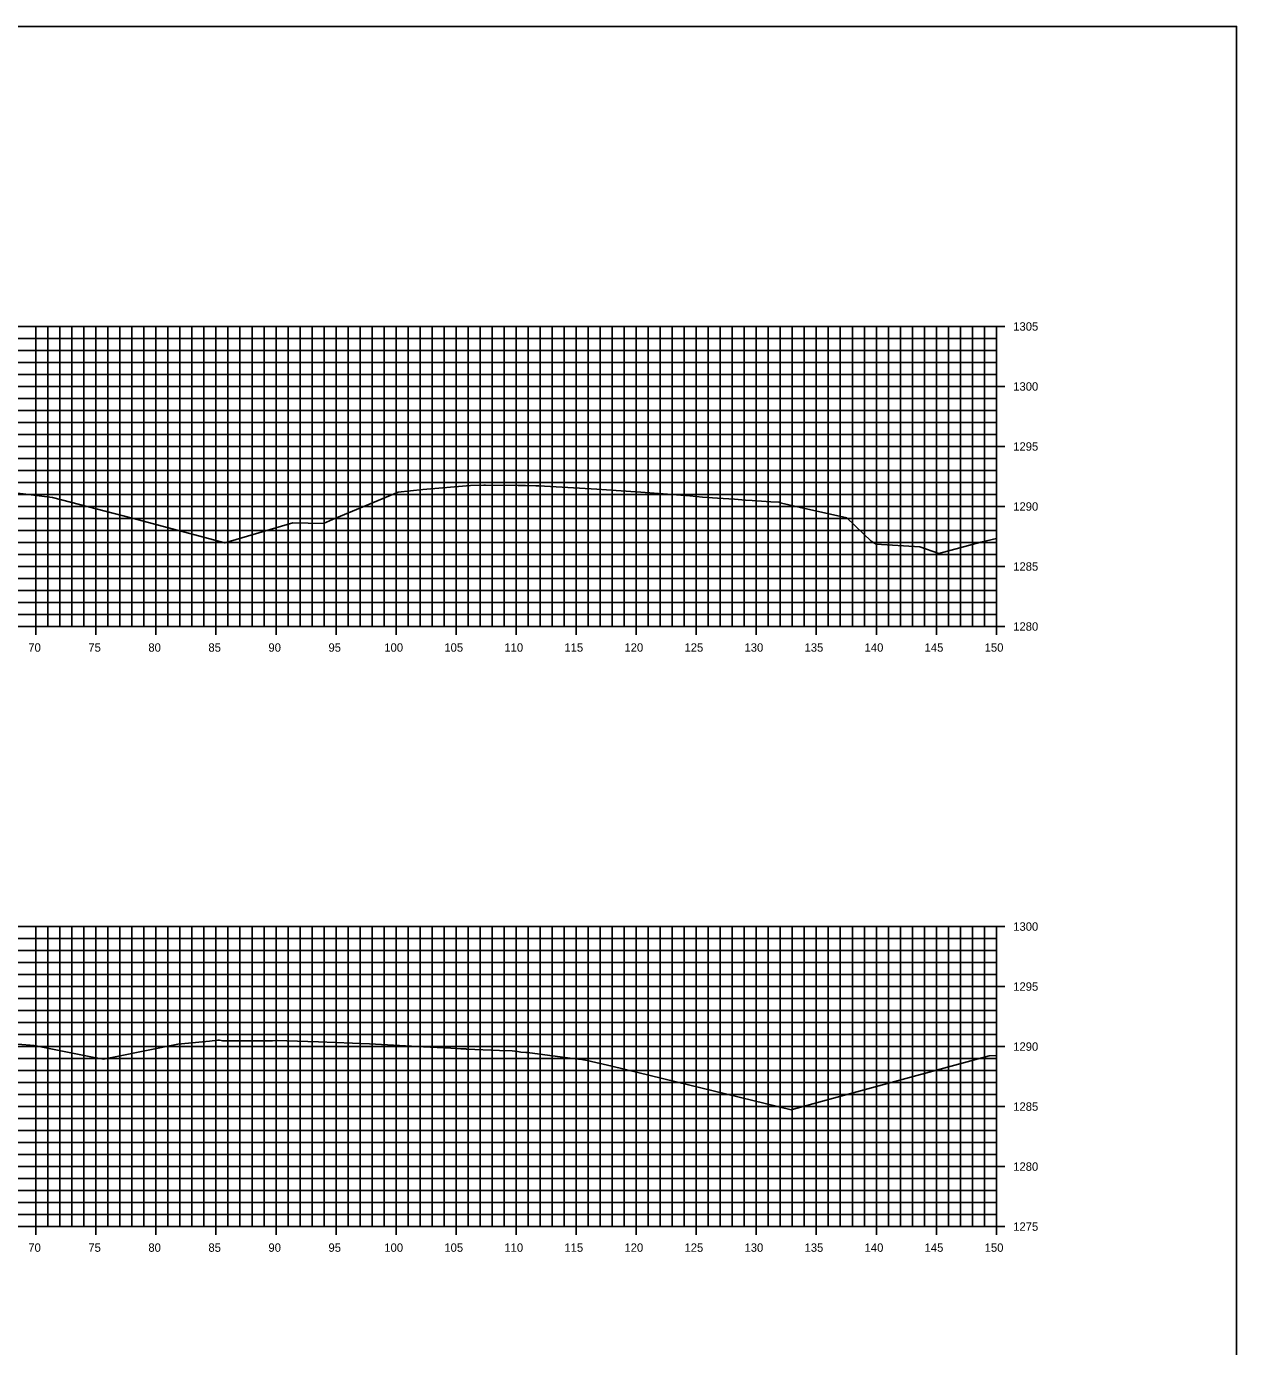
# Model space of a CAD drawing. Extents: x 674939 to 678919, y 750652 to 765176.
# Drawn here: x 678817.7 to 678918.5, y 757702.6 to 757812.6 of the extents above; entities that cross this region are included whole.
import ezdxf

# ---------------------------------------------------------------- set-up
doc = ezdxf.new("R2010")
doc.units = 0
for name, color, linetype in [('R_Axis', 7, 'Continuous'), ('R_Axis Annot', 7, 'Continuous'), ('R_Exist Surface', 7, 'Continuous'), ('R_Grid', 7, 'Continuous'), ('R_No Plot', 7, 'Continuous')]:
    doc.layers.add(name, color=color, linetype=linetype)

msp = doc.modelspace()

# ---------------------------------------------------------------- linework, layer by layer
at = {"layer": 'R_Axis'}
for p, q in [((678899.23, 757787.55), (678897.83, 757787.55)), ((678898.53, 757762.55), (678898.53, 757787.55)), ((678899.23, 757782.55), (678897.83, 757782.55)), ((678899.23, 757777.55), (678897.83, 757777.55)), ((678899.23, 757772.55), (678897.83, 757772.55)), ((678899.23, 757767.55), (678897.83, 757767.55)), ((678598.53, 757762.55), (678898.53, 757762.55)), ((678818.53, 757761.85), (678818.53, 757763.25)), ((678823.53, 757761.85), (678823.53, 757763.25)), ((678828.53, 757761.85), (678828.53, 757763.25)), ((678833.53, 757761.85), (678833.53, 757763.25)), ((678838.53, 757761.85), (678838.53, 757763.25)), ((678843.53, 757761.85), (678843.53, 757763.25)), ((678848.53, 757761.85), (678848.53, 757763.25)), ((678853.53, 757761.85), (678853.53, 757763.25)), ((678858.53, 757761.85), (678858.53, 757763.25)), ((678863.53, 757761.85), (678863.53, 757763.25)), ((678868.53, 757761.85), (678868.53, 757763.25)), ((678873.53, 757761.85), (678873.53, 757763.25)), ((678878.53, 757761.85), (678878.53, 757763.25)), ((678883.53, 757761.85), (678883.53, 757763.25)), ((678888.53, 757761.85), (678888.53, 757763.25)), ((678893.53, 757761.85), (678893.53, 757763.25)), ((678899.23, 757762.55), (678897.83, 757762.55)), ((678898.53, 757761.85), (678898.53, 757763.25)), ((678899.23, 757737.55), (678897.83, 757737.55)), ((678898.53, 757712.55), (678898.53, 757737.55)), ((678899.23, 757732.55), (678897.83, 757732.55)), ((678899.23, 757727.55), (678897.83, 757727.55)), ((678899.23, 757722.55), (678897.83, 757722.55)), ((678899.23, 757717.55), (678897.83, 757717.55)), ((678818.53, 757711.85), (678818.53, 757713.25)), ((678823.53, 757711.85), (678823.53, 757713.25)), ((678828.53, 757711.85), (678828.53, 757713.25)), ((678833.53, 757711.85), (678833.53, 757713.25)), ((678838.53, 757711.85), (678838.53, 757713.25)), ((678843.53, 757711.85), (678843.53, 757713.25)), ((678848.53, 757711.85), (678848.53, 757713.25)), ((678853.53, 757711.85), (678853.53, 757713.25)), ((678858.53, 757711.85), (678858.53, 757713.25)), ((678863.53, 757711.85), (678863.53, 757713.25)), ((678868.53, 757711.85), (678868.53, 757713.25)), ((678873.53, 757711.85), (678873.53, 757713.25)), ((678878.53, 757711.85), (678878.53, 757713.25)), ((678883.53, 757711.85), (678883.53, 757713.25)), ((678888.53, 757711.85), (678888.53, 757713.25)), ((678893.53, 757711.85), (678893.53, 757713.25)), ((678898.53, 757711.85), (678898.53, 757713.25)), ((678598.53, 757712.55), (678898.53, 757712.55)), ((678899.23, 757712.55), (678897.83, 757712.55))]:
    msp.add_line(p, q, dxfattribs=at)
at = {"layer": 'R_Exist Surface'}
for points in [[(678814.53, 757773.97), (678819.91, 757773.29), (678826.55, 757771.58), (678834.27, 757769.51), (678839.92, 757771.18), (678842.49, 757771.12), (678843.23, 757771.46), (678848.7, 757773.74), (678850.76, 757773.97), (678854.73, 757774.31), (678854.73, 757774.31), (678855.83, 757774.34), (678855.97, 757774.34), (678858.71, 757774.3), (678859.2, 757774.29), (678859.31, 757774.29), (678860.17, 757774.28), (678860.42, 757774.27), (678865.25, 757773.99), (678866.87, 757773.89), (678868.92, 757773.74), (678872.99, 757773.43), (678874.05, 757773.33), (678875.3, 757773.23), (678876.72, 757773.15), (678877.64, 757773.09), (678878.19, 757773.06), (678879.73, 757772.95), (678880.43, 757772.9), (678880.53, 757772.85), (678880.64, 757772.84), (678882.21, 757772.46), (678886.07, 757771.6), (678888.11, 757769.65), (678888.51, 757769.41), (678892.15, 757769.19), (678893.72, 757768.63), (678897.24, 757769.57), (678898.53, 757769.89)], [(678815.66, 757727.87), (678818.38, 757727.65), (678823.24, 757726.68), (678824.15, 757726.51), (678825.27, 757726.72), (678830.36, 757727.74), (678832.98, 757728), (678833.69, 757728.09), (678833.82, 757728.07), (678834.09, 757728.02), (678835.63, 757728.03), (678837.96, 757728.04), (678838.25, 757728.04), (678838.65, 757728.05), (678839.43, 757728.04), (678842.07, 757727.94), (678846.32, 757727.77), (678850.82, 757727.54), (678853.08, 757727.41), (678853.91, 757727.37), (678854.21, 757727.35), (678854.34, 757727.35), (678854.39, 757727.34), (678857.14, 757727.22), (678858.2, 757727.19), (678858.63, 757727.14), (678858.93, 757727.09), (678859.34, 757727.06), (678859.55, 757727.06), (678859.67, 757727.04), (678863.45, 757726.53), (678864, 757726.46), (678864.44, 757726.4), (678866.51, 757725.91), (678881.44, 757722.28), (678881.63, 757722.33), (678884.35, 757723.08), (678897.02, 757726.54), (678897.92, 757726.79), (678898.53, 757726.8)]]:
    msp.add_lwpolyline(points, dxfattribs=at)
at = {"layer": 'R_Grid'}
for p, q in [((678598.53, 757787.55), (678898.53, 757787.55)), ((678818.53, 757762.55), (678818.53, 757787.55)), ((678819.53, 757762.55), (678819.53, 757787.55)), ((678820.53, 757762.55), (678820.53, 757787.55)), ((678821.53, 757762.55), (678821.53, 757787.55)), ((678822.53, 757762.55), (678822.53, 757787.55)), ((678823.53, 757762.55), (678823.53, 757787.55)), ((678824.53, 757762.55), (678824.53, 757787.55)), ((678825.53, 757762.55), (678825.53, 757787.55)), ((678826.53, 757762.55), (678826.53, 757787.55)), ((678827.53, 757762.55), (678827.53, 757787.55)), ((678828.53, 757762.55), (678828.53, 757787.55)), ((678829.53, 757762.55), (678829.53, 757787.55)), ((678830.53, 757762.55), (678830.53, 757787.55)), ((678831.53, 757762.55), (678831.53, 757787.55)), ((678832.53, 757762.55), (678832.53, 757787.55)), ((678833.53, 757762.55), (678833.53, 757787.55)), ((678834.53, 757762.55), (678834.53, 757787.55)), ((678835.53, 757762.55), (678835.53, 757787.55)), ((678836.53, 757762.55), (678836.53, 757787.55)), ((678837.53, 757762.55), (678837.53, 757787.55)), ((678838.53, 757762.55), (678838.53, 757787.55)), ((678839.53, 757762.55), (678839.53, 757787.55)), ((678840.53, 757762.55), (678840.53, 757787.55)), ((678841.53, 757762.55), (678841.53, 757787.55)), ((678842.53, 757762.55), (678842.53, 757787.55)), ((678843.53, 757762.55), (678843.53, 757787.55)), ((678844.53, 757762.55), (678844.53, 757787.55)), ((678845.53, 757762.55), (678845.53, 757787.55)), ((678846.53, 757762.55), (678846.53, 757787.55)), ((678847.53, 757762.55), (678847.53, 757787.55)), ((678848.53, 757762.55), (678848.53, 757787.55)), ((678849.53, 757762.55), (678849.53, 757787.55)), ((678850.53, 757762.55), (678850.53, 757787.55)), ((678851.53, 757762.55), (678851.53, 757787.55)), ((678852.53, 757762.55), (678852.53, 757787.55)), ((678853.53, 757762.55), (678853.53, 757787.55)), ((678854.53, 757762.55), (678854.53, 757787.55)), ((678855.53, 757762.55), (678855.53, 757787.55)), ((678856.53, 757762.55), (678856.53, 757787.55)), ((678857.53, 757762.55), (678857.53, 757787.55)), ((678858.53, 757762.55), (678858.53, 757787.55)), ((678859.53, 757762.55), (678859.53, 757787.55)), ((678860.53, 757762.55), (678860.53, 757787.55)), ((678861.53, 757762.55), (678861.53, 757787.55)), ((678862.53, 757762.55), (678862.53, 757787.55)), ((678863.53, 757762.55), (678863.53, 757787.55)), ((678864.53, 757762.55), (678864.53, 757787.55)), ((678865.53, 757762.55), (678865.53, 757787.55)), ((678866.53, 757762.55), (678866.53, 757787.55)), ((678867.53, 757762.55), (678867.53, 757787.55)), ((678868.53, 757762.55), (678868.53, 757787.55)), ((678869.53, 757762.55), (678869.53, 757787.55)), ((678870.53, 757762.55), (678870.53, 757787.55)), ((678871.53, 757762.55), (678871.53, 757787.55)), ((678872.53, 757762.55), (678872.53, 757787.55)), ((678873.53, 757762.55), (678873.53, 757787.55)), ((678874.53, 757762.55), (678874.53, 757787.55)), ((678875.53, 757762.55), (678875.53, 757787.55)), ((678876.53, 757762.55), (678876.53, 757787.55)), ((678877.53, 757762.55), (678877.53, 757787.55)), ((678878.53, 757762.55), (678878.53, 757787.55)), ((678879.53, 757762.55), (678879.53, 757787.55)), ((678880.53, 757762.55), (678880.53, 757787.55)), ((678881.53, 757762.55), (678881.53, 757787.55)), ((678882.53, 757762.55), (678882.53, 757787.55)), ((678883.53, 757762.55), (678883.53, 757787.55)), ((678884.53, 757762.55), (678884.53, 757787.55)), ((678885.53, 757762.55), (678885.53, 757787.55)), ((678886.53, 757762.55), (678886.53, 757787.55)), ((678887.53, 757762.55), (678887.53, 757787.55)), ((678888.53, 757762.55), (678888.53, 757787.55)), ((678889.53, 757762.55), (678889.53, 757787.55)), ((678890.53, 757762.55), (678890.53, 757787.55)), ((678891.53, 757762.55), (678891.53, 757787.55)), ((678892.53, 757762.55), (678892.53, 757787.55)), ((678893.53, 757762.55), (678893.53, 757787.55)), ((678894.53, 757762.55), (678894.53, 757787.55)), ((678895.53, 757762.55), (678895.53, 757787.55)), ((678896.53, 757762.55), (678896.53, 757787.55)), ((678897.53, 757762.55), (678897.53, 757787.55)), ((678898.53, 757762.55), (678898.53, 757787.55)), ((678598.53, 757786.55), (678898.53, 757786.55)), ((678598.53, 757785.55), (678898.53, 757785.55)), ((678598.53, 757784.55), (678898.53, 757784.55)), ((678598.53, 757783.55), (678898.53, 757783.55)), ((678598.53, 757782.55), (678898.53, 757782.55)), ((678598.53, 757781.55), (678898.53, 757781.55)), ((678598.53, 757780.55), (678898.53, 757780.55)), ((678598.53, 757779.55), (678898.53, 757779.55)), ((678598.53, 757778.55), (678898.53, 757778.55)), ((678598.53, 757777.55), (678898.53, 757777.55)), ((678598.53, 757776.55), (678898.53, 757776.55)), ((678598.53, 757775.55), (678898.53, 757775.55)), ((678598.53, 757774.55), (678898.53, 757774.55)), ((678598.53, 757773.55), (678898.53, 757773.55)), ((678598.53, 757772.55), (678898.53, 757772.55)), ((678598.53, 757771.55), (678898.53, 757771.55)), ((678598.53, 757770.55), (678898.53, 757770.55)), ((678598.53, 757769.55), (678898.53, 757769.55)), ((678598.53, 757768.55), (678898.53, 757768.55)), ((678598.53, 757767.55), (678898.53, 757767.55)), ((678598.53, 757766.55), (678898.53, 757766.55)), ((678598.53, 757765.55), (678898.53, 757765.55)), ((678598.53, 757764.55), (678898.53, 757764.55)), ((678598.53, 757763.55), (678898.53, 757763.55)), ((678598.53, 757762.55), (678898.53, 757762.55)), ((678598.53, 757737.55), (678898.53, 757737.55)), ((678818.53, 757712.55), (678818.53, 757737.55)), ((678819.53, 757712.55), (678819.53, 757737.55)), ((678820.53, 757712.55), (678820.53, 757737.55)), ((678821.53, 757712.55), (678821.53, 757737.55)), ((678822.53, 757712.55), (678822.53, 757737.55)), ((678823.53, 757712.55), (678823.53, 757737.55)), ((678824.53, 757712.55), (678824.53, 757737.55)), ((678825.53, 757712.55), (678825.53, 757737.55)), ((678826.53, 757712.55), (678826.53, 757737.55)), ((678827.53, 757712.55), (678827.53, 757737.55)), ((678828.53, 757712.55), (678828.53, 757737.55)), ((678829.53, 757712.55), (678829.53, 757737.55)), ((678830.53, 757712.55), (678830.53, 757737.55)), ((678831.53, 757712.55), (678831.53, 757737.55)), ((678832.53, 757712.55), (678832.53, 757737.55)), ((678833.53, 757712.55), (678833.53, 757737.55)), ((678834.53, 757712.55), (678834.53, 757737.55)), ((678835.53, 757712.55), (678835.53, 757737.55)), ((678836.53, 757712.55), (678836.53, 757737.55)), ((678837.53, 757712.55), (678837.53, 757737.55)), ((678838.53, 757712.55), (678838.53, 757737.55)), ((678839.53, 757712.55), (678839.53, 757737.55)), ((678840.53, 757712.55), (678840.53, 757737.55)), ((678841.53, 757712.55), (678841.53, 757737.55)), ((678842.53, 757712.55), (678842.53, 757737.55)), ((678843.53, 757712.55), (678843.53, 757737.55)), ((678844.53, 757712.55), (678844.53, 757737.55)), ((678845.53, 757712.55), (678845.53, 757737.55)), ((678846.53, 757712.55), (678846.53, 757737.55)), ((678847.53, 757712.55), (678847.53, 757737.55)), ((678848.53, 757712.55), (678848.53, 757737.55)), ((678849.53, 757712.55), (678849.53, 757737.55)), ((678850.53, 757712.55), (678850.53, 757737.55)), ((678851.53, 757712.55), (678851.53, 757737.55)), ((678852.53, 757712.55), (678852.53, 757737.55)), ((678853.53, 757712.55), (678853.53, 757737.55)), ((678854.53, 757712.55), (678854.53, 757737.55)), ((678855.53, 757712.55), (678855.53, 757737.55)), ((678856.53, 757712.55), (678856.53, 757737.55)), ((678857.53, 757712.55), (678857.53, 757737.55)), ((678858.53, 757712.55), (678858.53, 757737.55)), ((678859.53, 757712.55), (678859.53, 757737.55)), ((678860.53, 757712.55), (678860.53, 757737.55)), ((678861.53, 757712.55), (678861.53, 757737.55)), ((678862.53, 757712.55), (678862.53, 757737.55)), ((678863.53, 757712.55), (678863.53, 757737.55)), ((678864.53, 757712.55), (678864.53, 757737.55)), ((678865.53, 757712.55), (678865.53, 757737.55)), ((678866.53, 757712.55), (678866.53, 757737.55)), ((678867.53, 757712.55), (678867.53, 757737.55)), ((678868.53, 757712.55), (678868.53, 757737.55)), ((678869.53, 757712.55), (678869.53, 757737.55)), ((678870.53, 757712.55), (678870.53, 757737.55)), ((678871.53, 757712.55), (678871.53, 757737.55)), ((678872.53, 757712.55), (678872.53, 757737.55)), ((678873.53, 757712.55), (678873.53, 757737.55)), ((678874.53, 757712.55), (678874.53, 757737.55)), ((678875.53, 757712.55), (678875.53, 757737.55)), ((678876.53, 757712.55), (678876.53, 757737.55)), ((678877.53, 757712.55), (678877.53, 757737.55)), ((678878.53, 757712.55), (678878.53, 757737.55)), ((678879.53, 757712.55), (678879.53, 757737.55)), ((678880.53, 757712.55), (678880.53, 757737.55)), ((678881.53, 757712.55), (678881.53, 757737.55)), ((678882.53, 757712.55), (678882.53, 757737.55)), ((678883.53, 757712.55), (678883.53, 757737.55)), ((678884.53, 757712.55), (678884.53, 757737.55)), ((678885.53, 757712.55), (678885.53, 757737.55)), ((678886.53, 757712.55), (678886.53, 757737.55)), ((678887.53, 757712.55), (678887.53, 757737.55)), ((678888.53, 757712.55), (678888.53, 757737.55)), ((678889.53, 757712.55), (678889.53, 757737.55)), ((678890.53, 757712.55), (678890.53, 757737.55)), ((678891.53, 757712.55), (678891.53, 757737.55)), ((678892.53, 757712.55), (678892.53, 757737.55)), ((678893.53, 757712.55), (678893.53, 757737.55)), ((678894.53, 757712.55), (678894.53, 757737.55)), ((678895.53, 757712.55), (678895.53, 757737.55)), ((678896.53, 757712.55), (678896.53, 757737.55)), ((678897.53, 757712.55), (678897.53, 757737.55)), ((678898.53, 757712.55), (678898.53, 757737.55)), ((678598.53, 757736.55), (678898.53, 757736.55)), ((678598.53, 757735.55), (678898.53, 757735.55)), ((678598.53, 757734.55), (678898.53, 757734.55)), ((678598.53, 757733.55), (678898.53, 757733.55)), ((678598.53, 757732.55), (678898.53, 757732.55)), ((678598.53, 757731.55), (678898.53, 757731.55)), ((678598.53, 757730.55), (678898.53, 757730.55)), ((678598.53, 757729.55), (678898.53, 757729.55)), ((678598.53, 757728.55), (678898.53, 757728.55)), ((678598.53, 757727.55), (678898.53, 757727.55)), ((678598.53, 757726.55), (678898.53, 757726.55)), ((678598.53, 757725.55), (678898.53, 757725.55)), ((678598.53, 757724.55), (678898.53, 757724.55)), ((678598.53, 757723.55), (678898.53, 757723.55)), ((678598.53, 757722.55), (678898.53, 757722.55)), ((678598.53, 757721.55), (678898.53, 757721.55)), ((678598.53, 757720.55), (678898.53, 757720.55)), ((678598.53, 757719.55), (678898.53, 757719.55)), ((678598.53, 757718.55), (678898.53, 757718.55)), ((678598.53, 757717.55), (678898.53, 757717.55)), ((678598.53, 757716.55), (678898.53, 757716.55)), ((678598.53, 757715.55), (678898.53, 757715.55)), ((678598.53, 757714.55), (678898.53, 757714.55)), ((678598.53, 757713.55), (678898.53, 757713.55)), ((678598.53, 757712.55), (678898.53, 757712.55))]:
    msp.add_line(p, q, dxfattribs=at)
at = {"layer": 'R_No Plot'}
msp.add_lwpolyline([(678578.53, 757592.55), (678918.53, 757592.55), (678918.53, 757812.55), (678578.53, 757812.55)], close=True, dxfattribs=at)

# ---------------------------------------------------------------- texts
at = {"layer": 'R_Axis Annot'}
for s, p in [('1305', (678899.93, 757787.2)), ('1300', (678899.93, 757782.2)), ('1295', (678899.93, 757777.2)), ('1290', (678899.93, 757772.2)), ('1285', (678899.93, 757767.2)), ('1280', (678899.93, 757762.2)), ('70', (678817.9, 757760.45)), ('75', (678822.9, 757760.45)), ('80', (678827.9, 757760.45)), ('85', (678832.9, 757760.45)), ('90', (678837.9, 757760.45)), ('95', (678842.9, 757760.45)), ('100', (678847.55, 757760.45)), ('105', (678852.55, 757760.45)), ('110', (678857.55, 757760.45)), ('115', (678862.55, 757760.45)), ('120', (678867.55, 757760.45)), ('125', (678872.55, 757760.45)), ('130', (678877.55, 757760.45)), ('135', (678882.55, 757760.45)), ('140', (678887.55, 757760.45)), ('145', (678892.55, 757760.45)), ('150', (678897.55, 757760.45)), ('1300', (678899.93, 757737.2)), ('1295', (678899.93, 757732.2)), ('1290', (678899.93, 757727.2)), ('1285', (678899.93, 757722.2)), ('1280', (678899.93, 757717.2)), ('1275', (678899.93, 757712.2)), ('70', (678817.9, 757710.45)), ('75', (678822.9, 757710.45)), ('80', (678827.9, 757710.45)), ('85', (678832.9, 757710.45)), ('90', (678837.9, 757710.45)), ('95', (678842.9, 757710.45)), ('100', (678847.55, 757710.45)), ('105', (678852.55, 757710.45)), ('110', (678857.55, 757710.45)), ('115', (678862.55, 757710.45)), ('120', (678867.55, 757710.45)), ('125', (678872.55, 757710.45)), ('130', (678877.55, 757710.45)), ('135', (678882.55, 757710.45)), ('140', (678887.55, 757710.45)), ('145', (678892.55, 757710.45)), ('150', (678897.55, 757710.45))]:
    msp.add_text(s, height=0.7, dxfattribs=at).set_placement(p)

doc.saveas('drawing.dxf')
